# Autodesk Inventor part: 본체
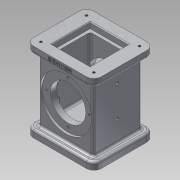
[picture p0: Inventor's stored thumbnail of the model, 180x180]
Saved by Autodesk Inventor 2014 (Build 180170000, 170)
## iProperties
Created: 2017-08
Part Number: 본체
Material: 알루미늄 6061
Document SubType Name: 모델링
Designer: user
Density: 2.71 g/cm^3
Appearance: 알루미늄 - 평지
Mass: 878.481 g
Surface Area: 642.803 cm^2
Volume: 324.163 cm^3
Author: user
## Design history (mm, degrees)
sketch "스케치2"
  geometry: L1 (46, -41)-(-46, -41); L2 (-46, -41)-(-46, 41); L3 (-46, 41)-(46, 41); L4 (46, 41)-(46, -41); L5 (46, -41)-(-46, 41); L6 (-46, -41)-(46, 41); 1 further point
  constraints: 12 end point, 2 midpoint, 2 parallel, 1 horizontal, 1 perpendicular
  dimensions: "d0" = 92 distance of L1.start L1.end; "d1" = 82 distance of L3.end L1.start
extrude "돌출1" join sketch "스케치2" distance "d2" = 10; taper "d3" = 0 deg
sketch "스케치3"
  geometry: L1 (-37, -33)-(37, -33); L2 (37, -33)-(37, 33); L3 (37, 33)-(-37, 33); L4 (-37, 33)-(-37, -33); L5 (-37, -33)-(37, 33); L6 (37, -33)-(-37, 33); 1 further point
  constraints: 12 end point, 2 midpoint, 2 parallel, 1 horizontal, 1 perpendicular
  dimensions: "d4" = 74 distance of L2.end L3.end; "d5" = 66 distance of L1.end L2.end
extrude "돌출2" join sketch "스케치3" distance "d6" = 88; taper "d7" = 0 deg
sketch "스케치4"
  geometry: L1 (-46, -41)-(46, -41); L2 (46, -41)-(46, 41); L3 (46, 41)-(-46, 41); L4 (-46, 41)-(-46, -41); L5 (-46, -41)-(46, 41); L6 (46, -41)-(-46, 41); 1 further point
  constraints: 12 end point, 2 midpoint, 2 parallel, 1 horizontal, 1 perpendicular
extrude "돌출3" join sketch "스케치4" distance "d8" = 10; taper "d9" = 0 deg
sketch "스케치5"
  geometry: L1 (83, -10)-(-9, -10) reference; C1 r 35 at (37, 44); 1 further point
  constraints: 1 centre point
  dimensions: "d10" = 54 distance from line of L1 C1.centre; "d11" = 70 diameter of C1
extrude "돌출4" cut sketch "스케치5" distance "d12" = 3; taper "d13" = 0 deg
sketch "스케치6"
  geometry: C1 r 35 at (0, 0) reference; C2 r 24 at (0, 0); 1 further point
  constraints: 1 centre point, 1 coincident
  dimensions: "d14" = 48 diameter of C2
extrude "돌출5" cut sketch "스케치6" distance "d15" = 8; taper "d16" = 0 deg
sketch "스케치7"
  geometry: L1 (-26, -26)-(26, -26); L2 (26, -26)-(26, 26); L3 (26, 26)-(-26, 26); L4 (-26, 26)-(-26, -26); L5 (-26, -26)-(26, 26); L6 (26, -26)-(-26, 26); 1 further point
  constraints: 12 end point, 2 midpoint, 2 parallel, 1 horizontal, 1 perpendicular
  dimensions: "d17" = 52 distance of L3.end L2.end; "d18" = 52 distance of L1.end L2.end
extrude "돌출6" cut sketch "스케치7" distance "d19" = 8; taper "d20" = 0 deg
sketch "스케치8"
  geometry: L1 (-22, -22)-(22, -22); L2 (22, -22)-(22, 22); L3 (22, 22)-(-22, 22); L4 (-22, 22)-(-22, -22); L5 (-22, -22)-(22, 22); L6 (22, -22)-(-22, 22); 1 further point
  constraints: 12 end point, 2 midpoint, 2 parallel, 1 horizontal, 1 perpendicular
  dimensions: "d21" = 44 distance of L3.end L2.end; "d22" = 44 distance of L1.end L2.end
extrude "돌출7" cut sketch "스케치8" distance "d23" = 74; taper "d24" = 0 deg
sketch "스케치9"
  geometry: L1 (-24, -24)-(24, -24); L2 (24, -24)-(24, 24); L3 (24, 24)-(-24, 24); L4 (-24, 24)-(-24, -24); L5 (-24, -24)-(24, 24); L6 (24, -24)-(-24, 24); 1 further point
  constraints: 12 end point, 2 midpoint, 2 parallel, 1 horizontal, 1 perpendicular
  dimensions: "d25" = 48 distance of L1.end L2.end; "d26" = 48 distance of L2.end L3.end
extrude "돌출8" cut sketch "스케치9" distance "d27" = 16; taper "d28" = 0 deg
sketch "스케치10" dims "d29" = 58
  geometry: C1 r 35 at (0, 0) reference; 3 further points
  constraints: 1 coincident, 1 vertical alignment, 2 other
hole "구멍1" sketch "스케치10" at (0, 29) diameter "d30" = 3.242; stored, may be unused: countersink angle "d34" = 90 deg, drill point angle "d36" = 118 deg; dims "d31" = 4, "d32" = 4, "d33" = 2, "d35" = 6
sketch "스케치11"
  geometry: L1 (46, 41)-(-46, 41) reference; L2 (-46, 41)-(-46, -41) reference; 2 further points
  dimensions: "d40" = 10 distance from line of L1 point (-36, 31); "d41" = 10 distance from line of point (-36, 31) L2
hole "구멍2" sketch "스케치11" at (-36, 31) diameter "d42" = 3.242; stored, may be unused: countersink angle "d46" = 90 deg, drill point angle "d48" = 118 deg; dims "d43" = 4, "d44" = 4, "d45" = 2, "d47" = 6
node "작업 평면1"
fillet "모깎기1" dims "d50" = 10
sketch "스케치12"
  geometry: L1 (10, 64)-(10, 2) reference; 3 further points
  dimensions: "d51" = 38 distance from line of L1 point (-28, 33); "d52" = 42 distance of point (-28, 33) point (-70, 33)
hole "구멍3" sketch "스케치12" at (-28, 33), (-70, 33) diameter "d53" = 4.134; stored, may be unused: countersink angle "d57" = 90 deg, drill point angle "d59" = 118 deg; dims "d54" = 4, "d55" = 4, "d56" = 2, "d58" = 6
fillet "모깎기2" dims "d60" = 3
fillet "모깎기3" dims "d61" = 3
fillet "모깎기4" dims "d62" = 3
fillet "모깎기5" dims "d63" = 3
chamfer "모따기1" distance "d64" = 1; stored, may be unused: second distance "d65" = 2, angle "d66" = 45 deg
sketch "스케치13"
  geometry: L1 (0, 0)-(72, 0) reference; L2 (19.446, -1.598)-(52.554, -1.598); L3 (52.554, -1.598)-(52.554, -6.402); L4 (52.554, -6.402)-(19.446, -6.402); L5 (19.446, -6.402)-(19.446, -1.598); L6 (36, -1.598)-(36, -6.402); L7 (19.446, -4)-(36, -4); L8 (-10, 0)-(-10, -7) reference; 1 further point
  constraints: 4 end point, 4 midpoint, 2 other
  dimensions: "d67" = 4 distance between parallel lines of L1 L7; "d68" = 46 distance between parallel lines of L6 L8
feature "엠보싱1" sketch "스케치13" dims "d69" = 0.5, "d70" = 0, "GapSize" = 0.5 (= Thickness), "SeamGap" = 0.01, "Thickness" = 0.5, "BendRadius" = 0.5 (= Thickness), "MinimumRemnant" = 1 (= 2 x Thickness), "BendReliefDepth" = 0.25 (= 0.5 x Thickness), "BendReliefWidth" = 0.5 (= Thickness), "CornerReliefSize" = 2 (= 4 x Thickness), "JacobiRadiusSize" = 0.5 (= BendRadius), "TransitionRadius" = 0.5 (= BendRadius)
node "솔리드1"
mirror "대칭1"
pattern_circular "원형 패턴1" dims angle "d38" = 360 deg
mirror "대칭2"
mirror "대칭3"
mirror "대칭4"
mirror "대칭5"
other parameters: "d49" = -54
